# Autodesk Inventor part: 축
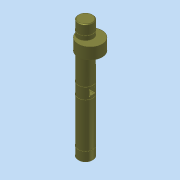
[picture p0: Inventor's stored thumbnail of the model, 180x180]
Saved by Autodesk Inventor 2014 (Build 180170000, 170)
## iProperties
Company: 한국ATC센터
Created: 2015-04
Part Number: 축
Document SubType Name: Modeling
Designer: KYOUNG IL JANG
Density: 1 g/cm^3
Material: 일반
Mass: 77.3127 g
Surface Area: 163.755 cm^2
Volume: 77.3127 cm^3
Appearance: 티타늄
Author: KYOUNG IL JANG
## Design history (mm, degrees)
sketch "스케치1"
  geometry: C1 r 11 at (0, 0); 1 further point
  constraints: 1 centre point, 1 coincident
  dimensions: "d0" = 22 diameter of C1
extrude "돌출1" new body sketch "스케치1" stored distance "d1" = 180; taper "d2" = 0 deg
sketch "스케치2"
  geometry: L1 (-10.247, -4)-(10.247, -4); L2 (-10.247, 4)-(10.247, 4); A1 r 11 centre (0, 0) between (-10.247, -4) and (10.247, -4) reference; 1 further point
  constraints: 4 end point, 4 point on circle, 2 parallel, 1 horizontal
  dimensions: "d3" = 8 distance between parallel lines of L2 L1
extrude "돌출2" cut sketch "스케치2" stored distance "d4" = 8; taper "d5" = 0 deg
sketch "스케치3"
  geometry: 5 further points
hole "구멍1" sketch "스케치3" at (-4, 4), (4, 4), (4, -4), (-4, -4) diameter "d6" = 2; stored, may be unused: countersink angle "d10" = 90 deg, drill point angle "d12" = 118 deg; dims "d7" = 6, "d8" = 4, "d9" = 2, "d11" = 8
chamfer "모따기1" distance "d13" = 1; stored, may be unused: second distance "d14" = 2, angle "d15" = 45 deg
sketch "스케치4"
  geometry: L1 (-10, 9)-(-11, 9); L2 (-11, 9)-(-11, 7.8); L3 (-11, 7.8)-(-10, 7.8); L4 (-10, 7.8)-(-10, 9); L5 (-10, 90)-(10, 90) reference; L6 (0, -15)-(0, 90) reference; L7 (-10, 74.8)-(-11, 74.8); L8 (-11, 74.8)-(-11, 76); L9 (-11, 76)-(-10, 76); L10 (-10, 76)-(-10, 74.8); 1 further point
  constraints: 16 end point, 4 parallel, 2 equal length, 2 horizontal, 2 perpendicular, 1 collinear
  dimensions: "d16" = 7.8 distance from line of L3 point (0, 0); "d17" = 82.2 distance between parallel lines of L3 L5 (derived); "d18" = 11 distance from line of point (0, 0) L2; "d19" = 1 distance of L2.end L3.end; "d20" = 1.2 distance of L1.end L2.end; "d27" = 14 distance between parallel lines of L5 L9
revolve "회전1" sketch "스케치4" stored, may be unused: angle "d21" = 90 deg
sketch "스케치5"
  geometry: L1 (11, 52)-(-7, 52); L2 (-7, 52)-(-7, 69); L3 (-7, 69)-(11, 69); L4 (11, 69)-(11, 52); 1 further point
  constraints: 8 end point, 2 parallel, 1 horizontal, 1 perpendicular
  dimensions: "d22" = 17 distance of L3.end L1.start; "d23" = 36 diameter of L4 L2; "d24" = 7 horizontal distance of L2.end point (0, 0); "d25" = 52 distance from line of L1 point (0, 0)
revolve "회전2" sketch "스케치5" stored, may be unused: angle "d26" = 90 deg
node "솔리드1"
mirror "대칭1"
mirror "대칭2"
